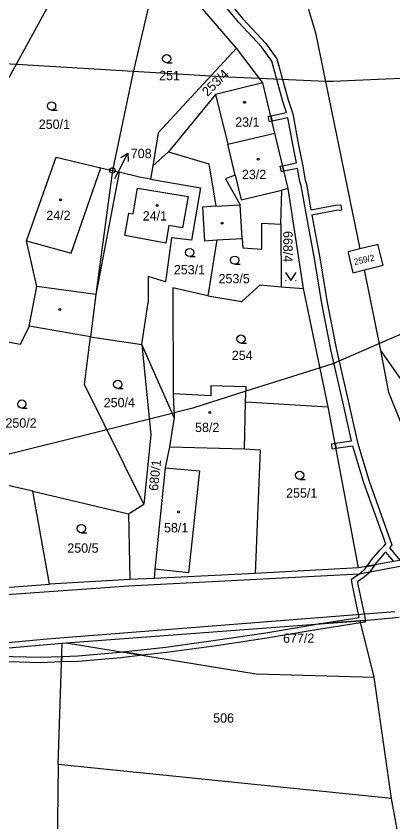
# Model space of a CAD drawing. Extents: x -747333 to -745433, y -1133152 to -1130600.
# Drawn here: x -746401.2 to -746332.5, y -1132365.2 to -1132218.2 of the extents above; entities that cross this region are included whole.
import ezdxf

# ---------------------------------------------------------------- set-up
doc = ezdxf.new("R2010")
doc.units = 0
for name, color, linetype in [('Vrstva 1', 7, 'Continuous'), ('Vrstva 16', 7, 'Continuous'), ('Vrstva 18', 7, 'Continuous'), ('Vrstva 19', 7, 'Continuous'), ('Vrstva 24', 7, 'Continuous'), ('Vrstva 25', 7, 'Continuous'), ('Vrstva 3', 7, 'Continuous'), ('Vrstva 30', 7, 'Continuous'), ('Vrstva 37', 7, 'Continuous'), ('Vrstva 4', 7, 'Continuous'), ('Vrstva 52', 7, 'Continuous'), ('Vrstva 6', 7, 'Continuous')]:
    doc.layers.add(name, color=color, linetype=linetype)

msp = doc.modelspace()

# ---------------------------------------------------------------- linework, layer by layer
at = {"layer": 'Vrstva 1'}
for points in [[(-746387.86, -1132202.51), (-746402.53, -1132229.49)], [(-746375.2, -1132208.32), (-746379.95, -1132228.73)], [(-746361.01, -1132224.1), (-746374.1, -1132208.89)], [(-746349.14, -1132212.69), (-746346.6, -1132221.28)], [(-746346.6, -1132221.28), (-746338.5, -1132260.67)], [(-746361.01, -1132224.1), (-746375.33, -1132239.55)], [(-746356.19, -1132230.43), (-746361.01, -1132224.1)], [(-746379.95, -1132228.73), (-746383.65, -1132246.38)], [(-746356.19, -1132230.43), (-746364.83, -1132232.5)], [(-746354.02, -1132239.56), (-746356.19, -1132230.43)], [(-746364.83, -1132232.5), (-746373.4, -1132243.01)], [(-746375.33, -1132239.55), (-746376.31, -1132245.54)], [(-746362.62, -1132241.61), (-746354.02, -1132239.56)], [(-746351.62, -1132249.69), (-746354.02, -1132239.56)], [(-746361.26, -1132247.22), (-746362.62, -1132241.61)], [(-746373.4, -1132243.01), (-746376.31, -1132245.54)], [(-746373.4, -1132243.01), (-746366.05, -1132245.19)], [(-746399.35, -1132259.24), (-746393.93, -1132243.96)], [(-746393.93, -1132243.96), (-746385.74, -1132245.89)], [(-746366.05, -1132245.19), (-746364.79, -1132252.91)], [(-746383.65, -1132246.38), (-746386.66, -1132269.02)], [(-746382.45, -1132246.69), (-746386.66, -1132269.02)], [(-746385.74, -1132245.89), (-746383.65, -1132246.38)], [(-746383.65, -1132246.38), (-746382.45, -1132246.69)], [(-746378.69, -1132247.61), (-746382.45, -1132246.69)], [(-746376.31, -1132245.54), (-746376.71, -1132247.95)], [(-746376.71, -1132247.95), (-746378.69, -1132247.61)], [(-746376.71, -1132247.95), (-746367.58, -1132249.53)], [(-746361.26, -1132247.22), (-746363.05, -1132247.88)], [(-746363.05, -1132247.88), (-746360.38, -1132252.64)], [(-746367.58, -1132249.53), (-746369.24, -1132259.11)], [(-746351.62, -1132249.69), (-746352.78, -1132249.96)], [(-746348.82, -1132267.93), (-746351.62, -1132249.69)], [(-746352.94, -1132256.15), (-746352.78, -1132249.96)], [(-746360, -1132258.78), (-746360.38, -1132252.64)], [(-746364.79, -1132252.91), (-746367.22, -1132253.06)], [(-746367.22, -1132253.06), (-746366.84, -1132259.2)], [(-746356.42, -1132260.75), (-746356.38, -1132256.01)], [(-746356.38, -1132256.01), (-746352.94, -1132256.15)], [(-746352.94, -1132256.15), (-746352.9, -1132267.59)], [(-746397.47, -1132267.55), (-746399.35, -1132259.24)], [(-746372.85, -1132258.64), (-746373.96, -1132266.7)], [(-746369.24, -1132259.11), (-746372.85, -1132258.64)], [(-746366.84, -1132259.2), (-746364.59, -1132259.06)], [(-746364.59, -1132259.06), (-746366.22, -1132269.26)], [(-746364.59, -1132259.06), (-746360, -1132258.78)], [(-746360, -1132258.78), (-746359.86, -1132260.47)], [(-746335.2, -1132259.86), (-746338.5, -1132260.67)], [(-746335.15, -1132260.05), (-746335.2, -1132259.86)], [(-746359.86, -1132260.47), (-746356.42, -1132260.75)], [(-746338.5, -1132260.67), (-746340.67, -1132261.21)], [(-746340.67, -1132261.21), (-746340.62, -1132261.4)], [(-746340.62, -1132261.4), (-746339.84, -1132264.84)], [(-746334.31, -1132263.47), (-746335.15, -1132260.05)], [(-746337.67, -1132264.5), (-746334.26, -1132263.66)], [(-746334.26, -1132263.66), (-746334.31, -1132263.47)], [(-746377.15, -1132265.72), (-746377.13, -1132270.44)], [(-746373.96, -1132266.7), (-746377.15, -1132265.72)], [(-746339.84, -1132264.84), (-746339.8, -1132265.03)], [(-746339.8, -1132265.03), (-746337.67, -1132264.5)], [(-746334.69, -1132279.22), (-746337.67, -1132264.5)], [(-746360.07, -1132270.26), (-746356.7, -1132267.27)], [(-746356.7, -1132267.27), (-746352.9, -1132267.59)], [(-746398.85, -1132274.79), (-746397.47, -1132267.55)], [(-746366.22, -1132269.26), (-746372.62, -1132267.81)], [(-746372.62, -1132267.81), (-746372.56, -1132287.12)], [(-746352.9, -1132267.59), (-746348.82, -1132267.93)], [(-746344.28, -1132289.52), (-746348.82, -1132267.93)], [(-746386.66, -1132269.02), (-746387.66, -1132276.75)], [(-746366.22, -1132269.26), (-746360.07, -1132270.26)], [(-746378.28, -1132278.15), (-746377.13, -1132270.44)], [(-746400.51, -1132278.11), (-746416.68, -1132275.01)], [(-746398.85, -1132274.79), (-746400.51, -1132278.11)], [(-746387.66, -1132276.75), (-746398.85, -1132274.79)], [(-746388.78, -1132285.42), (-746387.66, -1132276.75)], [(-746387.66, -1132276.75), (-746378.28, -1132278.15)], [(-746372.39, -1132291.44), (-746378.28, -1132278.15)], [(-746378.28, -1132278.15), (-746376.62, -1132294.6)], [(-746333.21, -1132286.86), (-746334.69, -1132279.22)], [(-746324.77, -1132293.34), (-746334.69, -1132279.22)], [(-746377.93, -1132307.24), (-746388.78, -1132285.42)], [(-746359.26, -1132285.83), (-746365.72, -1132285.66)], [(-746365.72, -1132285.66), (-746365.72, -1132287.5)], [(-746359.35, -1132288.57), (-746359.26, -1132285.83)], [(-746372.56, -1132287.12), (-746372.39, -1132291.44)], [(-746365.72, -1132287.5), (-746372.56, -1132287.12)], [(-746321.59, -1132315.77), (-746333.21, -1132286.86)], [(-746359.56, -1132297.17), (-746359.35, -1132288.57)], [(-746359.35, -1132288.57), (-746344.28, -1132289.52)], [(-746338.75, -1132318.87), (-746344.28, -1132289.52)], [(-746372.39, -1132291.44), (-746373.25, -1132296.77)], [(-746376.62, -1132294.6), (-746377.93, -1132307.24)], [(-746373.25, -1132296.77), (-746374.02, -1132300.61)], [(-746373.25, -1132296.77), (-746359.56, -1132297.17)], [(-746359.56, -1132297.17), (-746356.71, -1132297.35)], [(-746356.71, -1132297.35), (-746357.62, -1132319.89)], [(-746398.2, -1132304.9), (-746422.09, -1132299.47)], [(-746374.02, -1132300.61), (-746375.92, -1132319.08)], [(-746398.2, -1132304.9), (-746380.7, -1132309.01)], [(-746395.13, -1132321.84), (-746398.2, -1132304.9)], [(-746380.7, -1132309.01), (-746377.93, -1132307.24)], [(-746380.7, -1132309.01), (-746380.5, -1132320.99)], [(-746321.59, -1132315.77), (-746338.75, -1132318.87)], [(-746375.92, -1132319.08), (-746376.02, -1132320.81)], [(-746357.62, -1132319.89), (-746376.02, -1132320.81)], [(-746338.75, -1132318.87), (-746357.62, -1132319.89)], [(-746380.5, -1132320.99), (-746395.13, -1132321.84)], [(-746376.02, -1132320.81), (-746380.5, -1132320.99)], [(-746404.78, -1132322.59), (-746395.13, -1132321.84)], [(-746392.12, -1132332.53), (-746338.47, -1132328.52)], [(-746338.47, -1132328.52), (-746331.35, -1132327.82)], [(-746335.9, -1132338.8), (-746338.47, -1132328.52)], [(-746411.01, -1132334.18), (-746392.82, -1132332.59)], [(-746392.82, -1132332.59), (-746392.12, -1132332.53)], [(-746332.76, -1132360.93), (-746335.9, -1132338.8)], [(-746329.31, -1132379.55), (-746332.76, -1132360.93)]]:
    msp.add_lwpolyline(points, dxfattribs=at)
at = {"layer": 'Vrstva 16'}
msp.add_line((-746382.105116, -1132244.047372), (-746380.841524, -1132243.237535), dxfattribs=at)
for points in [[(-746382.68, -1132246.79), (-746380.841524, -1132243.237535), (-746380.772942, -1132244.7368)], [(-746383.22, -1132247.84), (-746382.68, -1132246.79)]]:
    msp.add_lwpolyline(points, dxfattribs=at)
at = {"layer": 'Vrstva 24'}
msp.add_line((-746383.7, -1132246.38), (-746383.6, -1132246.38), dxfattribs=at)
msp.add_circle((-746383.65, -1132246.38), 0.499289, dxfattribs=at)
at = {"layer": 'Vrstva 25'}
for p, q in [((-746373.76, -1132226.76), (-746372.76, -1132226.76)), ((-746394.76, -1132235.37), (-746393.76, -1132235.37)), ((-746369.55, -1132262.09), (-746368.55, -1132262.09)), ((-746361.34, -1132263.49), (-746360.34, -1132263.49)), ((-746352.06, -1132266.47), (-746351.96, -1132266.47)), ((-746350.26, -1132266.47), (-746350.16, -1132266.47)), ((-746360.2, -1132277.88), (-746359.2, -1132277.88)), ((-746382.68, -1132286.15), (-746381.68, -1132286.15)), ((-746400.18, -1132289.74), (-746399.18, -1132289.74)), ((-746349.49, -1132302.73), (-746348.49, -1132302.73)), ((-746389.33, -1132312.44), (-746388.33, -1132312.44))]:
    msp.add_line(p, q, dxfattribs=at)
msp.add_lwpolyline([(-746352.11, -1132264.97), (-746351.11, -1132266.47), (-746350.11, -1132264.97)], dxfattribs=at)
for centre, radius in [((-746373.76, -1132226.01), 0.75), ((-746394.76, -1132234.62), 0.75), ((-746359.54, -1132233.96), 0.174503), ((-746357.06, -1132244.31), 0.174503), ((-746393.1, -1132251.76), 0.174503), ((-746375.51, -1132252.76), 0.174503), ((-746363.66, -1132256.02), 0.174503), ((-746369.55, -1132261.34), 0.75), ((-746361.34, -1132262.74), 0.75), ((-746393.26, -1132271.76), 0.174503), ((-746360.2, -1132277.13), 0.75), ((-746382.68, -1132285.4), 0.75), ((-746400.18, -1132288.99), 0.75), ((-746365.89, -1132290.54), 0.174503), ((-746349.49, -1132301.98), 0.75), ((-746371.59, -1132308.63), 0.174503), ((-746389.33, -1132311.69), 0.75)]:
    msp.add_circle(centre, radius, dxfattribs=at)
at = {"layer": 'Vrstva 3'}
for points in [[(-746356.19, -1132230.43), (-746364.83, -1132232.5)], [(-746354.02, -1132239.56), (-746356.19, -1132230.43)], [(-746364.83, -1132232.5), (-746362.62, -1132241.61)], [(-746362.62, -1132241.61), (-746354.02, -1132239.56)], [(-746362.62, -1132241.61), (-746354.02, -1132239.56)], [(-746351.62, -1132249.69), (-746354.02, -1132239.56)], [(-746361.26, -1132247.22), (-746362.62, -1132241.61)], [(-746399.35, -1132259.24), (-746393.93, -1132243.96)], [(-746393.93, -1132243.96), (-746385.74, -1132245.89)], [(-746391.16, -1132261.46), (-746385.74, -1132245.89)], [(-746361.26, -1132247.22), (-746360.17, -1132251.72)], [(-746379.07, -1132249.64), (-746369.84, -1132251.15), (-746370.87, -1132256.87), (-746373.34, -1132256.42), (-746373.93, -1132259.62), (-746381.42, -1132258.26), (-746380.65, -1132254.15), (-746379.86, -1132254.3), (-746379.07, -1132249.64)], [(-746351.62, -1132249.69), (-746352.78, -1132249.96)], [(-746360.17, -1132251.72), (-746352.78, -1132249.96)], [(-746399.35, -1132259.24), (-746391.16, -1132261.46)], [(-746365.72, -1132285.66), (-746365.72, -1132287.5)], [(-746359.26, -1132285.83), (-746365.72, -1132285.66)], [(-746359.35, -1132288.57), (-746359.26, -1132285.83)], [(-746372.56, -1132287.12), (-746372.39, -1132291.44)], [(-746365.72, -1132287.5), (-746372.56, -1132287.12)], [(-746359.56, -1132297.17), (-746359.35, -1132288.57)], [(-746372.39, -1132291.44), (-746373.25, -1132296.77)], [(-746373.25, -1132296.77), (-746359.56, -1132297.17)], [(-746374.02, -1132300.61), (-746375.92, -1132319.08)], [(-746374.02, -1132300.61), (-746367.75, -1132301.19)], [(-746367.75, -1132301.19), (-746369.8, -1132319.75)], [(-746369.8, -1132319.75), (-746375.92, -1132319.08)]]:
    msp.add_lwpolyline(points, dxfattribs=at)
at = {"layer": 'Vrstva 30'}
for points in [[(-746365.03, -1132212.47), (-746359.84, -1132218.72)], [(-746360.58, -1132219.38), (-746365.45, -1132213.53)], [(-746359.84, -1132218.72), (-746355.68, -1132223.22)], [(-746356.45, -1132223.85), (-746360.58, -1132219.38)], [(-746355.68, -1132223.22), (-746353.65, -1132226.02)], [(-746354.57, -1132226.46), (-746356.45, -1132223.85)], [(-746353.65, -1132226.02), (-746351.58, -1132233.51)], [(-746352.54, -1132233.79), (-746354.57, -1132226.46)], [(-746351.58, -1132233.51), (-746350.75, -1132236.04)], [(-746351.87, -1132235.8), (-746352.54, -1132233.79)], [(-746355.22, -1132236.53), (-746354.76, -1132236.43)], [(-746354.76, -1132236.43), (-746351.87, -1132235.8)], [(-746354.53, -1132237.4), (-746354.76, -1132236.43)], [(-746354.76, -1132236.43), (-746354.53, -1132237.4)], [(-746350.75, -1132236.04), (-746349.73, -1132241.75)], [(-746355, -1132237.51), (-746355.22, -1132236.53)], [(-746354.53, -1132237.4), (-746355, -1132237.51)], [(-746351.63, -1132236.77), (-746354.53, -1132237.4)], [(-746350.71, -1132241.95), (-746351.63, -1132236.77)], [(-746350.06, -1132245.02), (-746350.71, -1132241.95)], [(-746349.73, -1132241.75), (-746348.98, -1132245.32)], [(-746352.6, -1132245.54), (-746350.06, -1132245.02)], [(-746348.98, -1132245.32), (-746348.47, -1132248.18)], [(-746353.03, -1132245.63), (-746352.6, -1132245.54)], [(-746352.83, -1132246.61), (-746353.03, -1132245.63)], [(-746352.37, -1132246.52), (-746352.83, -1132246.61)], [(-746352.37, -1132246.52), (-746352.6, -1132245.54)], [(-746352.6, -1132245.54), (-746352.37, -1132246.52)], [(-746349.87, -1132246), (-746352.37, -1132246.52)], [(-746349.45, -1132248.4), (-746349.87, -1132246)], [(-746348.47, -1132248.18), (-746348.27, -1132248.91)], [(-746349.25, -1132249.14), (-746349.45, -1132248.4)], [(-746348.32, -1132254.21), (-746349.25, -1132249.14)], [(-746348.27, -1132248.91), (-746347.43, -1132253.54)], [(-746342.95, -1132252.71), (-746341.98, -1132252.63)], [(-746341.98, -1132252.63), (-746341.89, -1132253.62)], [(-746347.43, -1132253.54), (-746342.95, -1132252.71)], [(-746342.82, -1132253.71), (-746347.25, -1132254.52)], [(-746341.89, -1132253.62), (-746342.82, -1132253.71)], [(-746346.81, -1132262.45), (-746348.32, -1132254.21)], [(-746347.25, -1132254.52), (-746345.83, -1132262.29)], [(-746345.44, -1132270.63), (-746346.81, -1132262.45)], [(-746345.83, -1132262.29), (-746344.46, -1132270.45)], [(-746343.76, -1132279.31), (-746345.44, -1132270.63)], [(-746344.46, -1132270.45), (-746342.78, -1132279.11)], [(-746342.78, -1132279.11), (-746340.64, -1132288.37)], [(-746341.62, -1132288.59), (-746343.76, -1132279.31)], [(-746340.04, -1132295.69), (-746341.62, -1132288.59)], [(-746340.64, -1132288.37), (-746338.95, -1132295.98)], [(-746343.69, -1132296.24), (-746343.04, -1132296.12)], [(-746343.51, -1132297.22), (-746343.69, -1132296.24)], [(-746343.04, -1132296.12), (-746342.61, -1132296.04)], [(-746342.85, -1132297.1), (-746343.04, -1132296.12)], [(-746343.04, -1132296.12), (-746342.85, -1132297.1)], [(-746342.61, -1132296.04), (-746340.04, -1132295.69)], [(-746339.8, -1132296.66), (-746342.45, -1132297.02)], [(-746337.78, -1132303.38), (-746339.8, -1132296.66)], [(-746338.95, -1132295.98), (-746336.84, -1132303.06)], [(-746342.85, -1132297.1), (-746343.51, -1132297.22)], [(-746342.45, -1132297.02), (-746342.85, -1132297.1)], [(-746333.8, -1132314.48), (-746337.78, -1132303.38)], [(-746336.84, -1132303.06), (-746332.68, -1132314.63)], [(-746336.36, -1132317.36), (-746334.81, -1132315.54)], [(-746334.81, -1132315.54), (-746334.12, -1132314.92)], [(-746334.12, -1132314.92), (-746333.8, -1132314.48)], [(-746332.68, -1132314.63), (-746333.12, -1132315.23)], [(-746333.12, -1132315.23), (-746331.16, -1132317.5)], [(-746334.09, -1132316.24), (-746335.58, -1132317.98)], [(-746333.8, -1132315.97), (-746334.09, -1132316.24)], [(-746332.3, -1132317.71), (-746333.8, -1132315.97)], [(-746337.6, -1132319.1), (-746337.24, -1132318.6)], [(-746337.24, -1132318.6), (-746336.36, -1132317.36)], [(-746335.84, -1132318.34), (-746337.24, -1132318.6)], [(-746337.24, -1132318.6), (-746335.84, -1132318.34)], [(-746335.84, -1132318.34), (-746336.84, -1132319.76)], [(-746335.58, -1132317.98), (-746335.84, -1132318.34)], [(-746340.05, -1132320.95), (-746338.34, -1132319.79)], [(-746338.34, -1132319.79), (-746337.6, -1132319.1)], [(-746336.84, -1132319.76), (-746337.71, -1132320.57)], [(-746339.84, -1132322.09), (-746340.05, -1132320.95)], [(-746337.71, -1132320.57), (-746338.95, -1132321.41)], [(-746338.95, -1132321.41), (-746338.86, -1132321.9)], [(-746338.63, -1132327.91), (-746339.84, -1132322.09)], [(-746338.86, -1132321.9), (-746337.63, -1132327.84)], [(-746347.77, -1132329.36), (-746346.08, -1132329.09)], [(-746338.38, -1132328.88), (-746347.61, -1132330.34)], [(-746346.08, -1132329.09), (-746338.63, -1132327.91)], [(-746346.08, -1132329.09), (-746338.47, -1132328.52)], [(-746338.47, -1132328.52), (-746346.08, -1132329.09)], [(-746338.47, -1132328.52), (-746337.57, -1132328.43)], [(-746337.57, -1132328.43), (-746338.47, -1132328.52)], [(-746337.54, -1132328.75), (-746338.38, -1132328.88)], [(-746337.63, -1132327.84), (-746337.57, -1132328.43)], [(-746337.57, -1132328.43), (-746337.54, -1132328.75)], [(-746355.64, -1132330.69), (-746347.77, -1132329.36)], [(-746347.61, -1132330.34), (-746355.48, -1132331.67)], [(-746364.83, -1132332.05), (-746355.64, -1132330.69)], [(-746355.48, -1132331.67), (-746364.69, -1132333.05)], [(-746381.84, -1132334.2), (-746373.92, -1132333.31)], [(-746373.92, -1132333.31), (-746364.83, -1132332.05)], [(-746364.69, -1132333.05), (-746373.79, -1132334.31)], [(-746404.46, -1132334.95), (-746396.81, -1132335.15)], [(-746392.9, -1132335.02), (-746389.96, -1132334.92)], [(-746389.96, -1132334.92), (-746382.23, -1132334.24)], [(-746382.23, -1132334.24), (-746381.84, -1132334.2)], [(-746378.16, -1132334.79), (-746382.13, -1132335.24)], [(-746378.16, -1132334.79), (-746381.84, -1132334.2)], [(-746381.84, -1132334.2), (-746378.16, -1132334.79)], [(-746373.79, -1132334.31), (-746378.16, -1132334.79)], [(-746396.81, -1132336.15), (-746404.51, -1132335.95)], [(-746396.81, -1132335.15), (-746392.9, -1132335.02)], [(-746392.93, -1132336.02), (-746396.81, -1132336.15)], [(-746392.9, -1132335.02), (-746392.93, -1132336.02)], [(-746392.93, -1132336.02), (-746392.9, -1132335.02)], [(-746389.9, -1132335.92), (-746392.93, -1132336.02)], [(-746382.13, -1132335.24), (-746389.9, -1132335.92)]]:
    msp.add_lwpolyline(points, dxfattribs=at)
at = {"layer": 'Vrstva 37'}
for centre in [(-746359.54, -1132233.96), (-746357.06, -1132244.31), (-746393.1, -1132251.76), (-746375.51, -1132252.76), (-746365.89, -1132290.54), (-746371.59, -1132308.63)]:
    msp.add_circle(centre, 0.174503, dxfattribs=at)
at = {"layer": 'Vrstva 4'}
for points in [[(-746364.83, -1132232.5), (-746362.62, -1132241.61)], [(-746391.16, -1132261.46), (-746385.74, -1132245.89)], [(-746361.26, -1132247.22), (-746360.17, -1132251.72)], [(-746379.07, -1132249.64), (-746369.84, -1132251.15), (-746370.87, -1132256.87), (-746373.34, -1132256.42), (-746373.93, -1132259.62), (-746381.42, -1132258.26), (-746380.65, -1132254.15), (-746379.86, -1132254.3), (-746379.07, -1132249.64)], [(-746360.17, -1132251.72), (-746352.78, -1132249.96)], [(-746364.79, -1132252.91), (-746360.38, -1132252.64)], [(-746399.35, -1132259.24), (-746391.16, -1132261.46)], [(-746386.66, -1132269.02), (-746397.47, -1132267.55)], [(-746374.02, -1132300.61), (-746367.75, -1132301.19)], [(-746367.75, -1132301.19), (-746369.8, -1132319.75)], [(-746321.12, -1132316.7), (-746338.63, -1132320.01)], [(-746338.63, -1132320.01), (-746380.7, -1132322.22)], [(-746369.8, -1132319.75), (-746375.92, -1132319.08)], [(-746380.7, -1132322.22), (-746404.7, -1132323.87)], [(-746395.58, -1132331.79), (-746332.14, -1132326.83)], [(-746426.75, -1132334.69), (-746395.58, -1132331.79)]]:
    msp.add_lwpolyline(points, dxfattribs=at)
at = {"layer": 'Vrstva 52'}
for points in [[(-746475.76, -1132213.59), (-746445.5, -1132221.62), (-746443.65, -1132221.91), (-746428.29, -1132224.24), (-746409.37, -1132227.12), (-746409.22, -1132227.11), (-746405.56, -1132226.75), (-746401.18, -1132227.01), (-746379.85, -1132228.29), (-746365.68, -1132229.14), (-746363.88, -1132229.25), (-746356.86, -1132229.55), (-746344.79, -1132230.07), (-746343.44, -1132230.12), (-746315.81, -1132228.88), (-746308.88, -1132227.43), (-746305.62, -1132226.75), (-746305.5, -1132226.74), (-746295, -1132225.5), (-746280.9, -1132218.43), (-746266.06, -1132211)], [(-746234.56, -1132253.13), (-746237.35, -1132253.31), (-746248.83, -1132254.09), (-746260.5, -1132254.87), (-746276.3, -1132257.54), (-746280.26, -1132258.21), (-746280.5, -1132258.25), (-746289.92, -1132261.35), (-746298.38, -1132264.13), (-746298.7, -1132264.24), (-746319.63, -1132271.37), (-746324.64, -1132273.53), (-746334.94, -1132277.97), (-746343.44, -1132281.63), (-746345.78, -1132282.37), (-746359.29, -1132286.66), (-746369, -1132289.75), (-746372.42, -1132290.61), (-746372.39, -1132291.44), (-746372.73, -1132290.68), (-746376.91, -1132291.73), (-746384.67, -1132293.68), (-746405.94, -1132299)]]:
    msp.add_lwpolyline(points, dxfattribs=at)
at = {"layer": 'Vrstva 6'}
for points in [[(-746393.53, -1132354.71), (-746392.82, -1132332.59)], [(-746392.12, -1132332.53), (-746357.42, -1132338.16)], [(-746357.42, -1132338.16), (-746335.9, -1132338.8)], [(-746393.53, -1132354.71), (-746393.81, -1132375.41)], [(-746332.76, -1132360.93), (-746393.53, -1132354.71)]]:
    msp.add_lwpolyline(points, dxfattribs=at)

# ---------------------------------------------------------------- texts
at = {"layer": 'Vrstva 16'}
msp.add_text('708', height=1.7, dxfattribs=at).set_placement((-746380.3, -1132244.13))
at = {"layer": 'Vrstva 18'}
for s, height, p in [('251', 1.7, (-746375.13, -1132229.92)), ('250/1', 1.7, (-746397.09, -1132238.8)), ('708', 0.1, (-746383.328027, -1132247.84)), ('253/1', 1.7, (-746372.45, -1132265.33)), ('253/5', 1.7, (-746364.29, -1132266.96)), ('254', 1.7, (-746361.87, -1132280.95)), ('250/4', 1.7, (-746385.24, -1132289.56)), ('250/2', 1.7, (-746403.17, -1132293.28)), ('255/1', 1.7, (-746351.97, -1132306.06)), ('250/5', 1.7, (-746391.88, -1132316.1)), ('677/2', 1.7, (-746352.52, -1132332.53)), ('506', 1.7, (-746365.27, -1132347.09))]:
    msp.add_text(s, height=height, dxfattribs=at).set_placement(p)
for s, height, rotation, p in [('253/4', 1.7, 45, (-746366.3, -1132232.99)), ('668/4', 1.7, 270, (-746352.49, -1132257.42)), ('259/2', 1.14, 12.73968, (-746339.47, -1132263.64)), ('680/1', 1.7, 84.01365, (-746375.36, -1132304.87))]:
    msp.add_text(s, height=height, rotation=rotation, dxfattribs=at).set_placement(p)
at = {"layer": 'Vrstva 19'}
for s, p in [('23/1', (-746361.25, -1132238.41)), ('23/2', (-746360.03, -1132247.97)), ('24/2', (-746395.719644, -1132255.42)), ('24/1', (-746378.116908, -1132255.51)), ('58/2', (-746368.58, -1132294.09)), ('58/1', (-746374.25, -1132312.39))]:
    msp.add_text(s, height=1.7, dxfattribs=at).set_placement(p)

doc.saveas('drawing.dxf')
